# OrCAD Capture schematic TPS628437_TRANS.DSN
size E
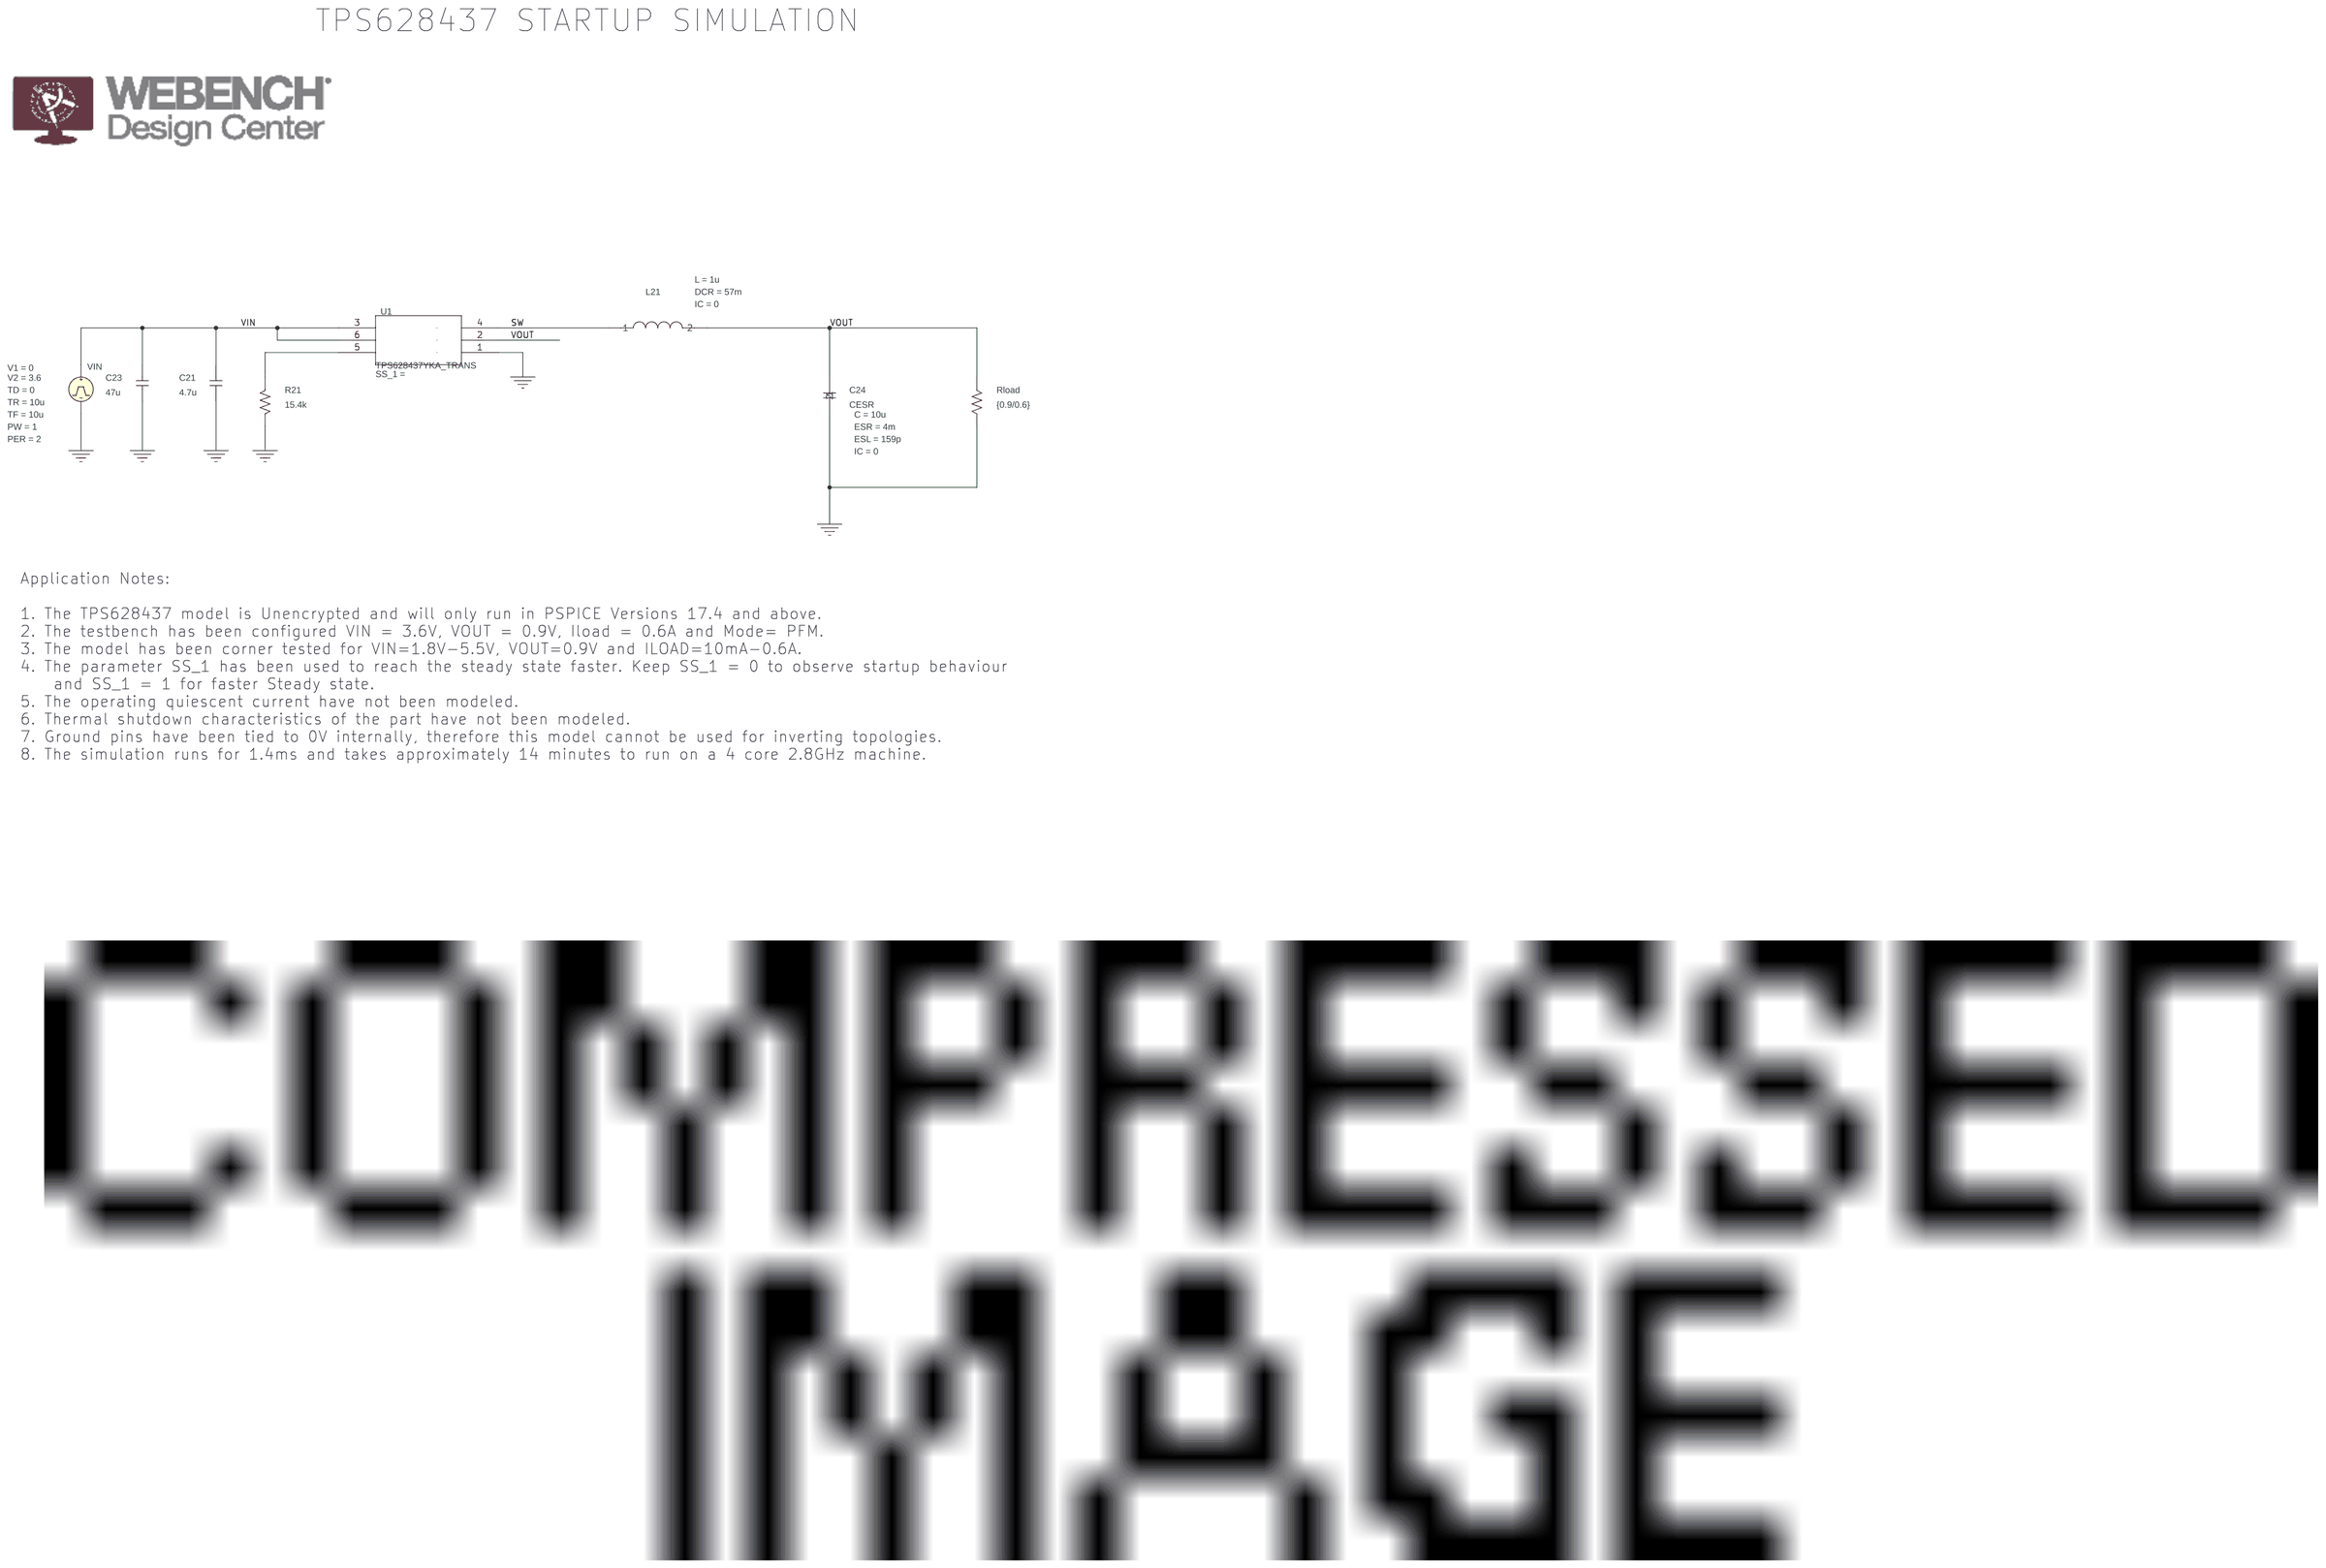
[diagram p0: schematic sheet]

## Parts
C21  4.7u  [RAD/CK05]
C23  47u  [RAD/CK05]
C24  CESR
L21  LDCR
R21  15.4k  [AX/RC05]
Rload  {0.9/0.6}  [AX/RC05]
U1  TPS628437YKA_TRANS  [YKA0006-IPC_A]
VIN  VPULSE

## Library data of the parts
C21 C23 = C
C24 = CESR: C: 10u; ESL: 159p; ESR: 4m; IC: 0; PSpiceTemplate: X^@REFDES %1 %2 @MODEL PARAMS: ?C|C=@C||C=10U| ?ESR|ESR=@ESR||ESR=2M| ?ESL|ESL=@ESL||ESL=1N| ?IC|IC=@IC||IC=0|
L21 = LDCR: DCR: 57m; IC: 0; L: 1u
R21 Rload = R
U1 = TPS628437YKA_TRANS
VIN = VPULSE: PER: 2; PW: 1; TD: 0; TF: 10u; TR: 10u; V1: 0; V2: 3.6

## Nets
VIN: C21.2 C23.2 U1.3(VIN) U1.6(EN) VIN.1(+)
0: C21.1 C23.1 C24.2 R21.2 Rload.2 U1.1(GND) VIN.2(-)
SW: L21.1 U1.4(SW)
VOUT: C24.1 L21.2 Rload.1 U1.2(VOS)
N16777420: R21.1 U1.5(VSET)

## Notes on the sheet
- TPS628437 STARTUP SIMULATION
- Application Notes:
  1. The TPS628437 model is Unencrypted and will only run in PSPICE Versions 17.4 and above.
  2. The testbench has been configured VIN = 3.6V, VOUT = 0.9V, Iload = 0.6A and Mode= PFM.
  3. The model has been corner tested for VIN=1.8V-5.5V, VOUT=0.9V and ILOAD=10mA-0.6A.
  4. The parameter SS_1 has been used to reach the steady state faster. Keep SS_1 = 0 to observe startup behaviour
      and SS_1 = 1 for faster Steady state.
  5. The operating quiescent current have not been modeled.
  6. Thermal shutdown characteristics of the part have not been modeled.
  7. Ground pins have been tied to 0V internally, therefore this model cannot be used for inverting topologies.
  8. The simulation runs for 1.4ms and takes approximately 14 minutes to run on a 4 core 2.8GHz machine.
